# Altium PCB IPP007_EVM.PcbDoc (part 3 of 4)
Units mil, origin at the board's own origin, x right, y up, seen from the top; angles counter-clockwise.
Board outline 3500.95 x 3103 mil, 6 copper layers (Top Layer, Int1 (GND), Int2 (Sign), Int3 (Sign), Int4 (GND), Bottom Layer), stack 61.068 mil thick; 257 components, 132 nets, 1052 pads, 535 vias.
Unrouted connection lines stored in the file: 3.
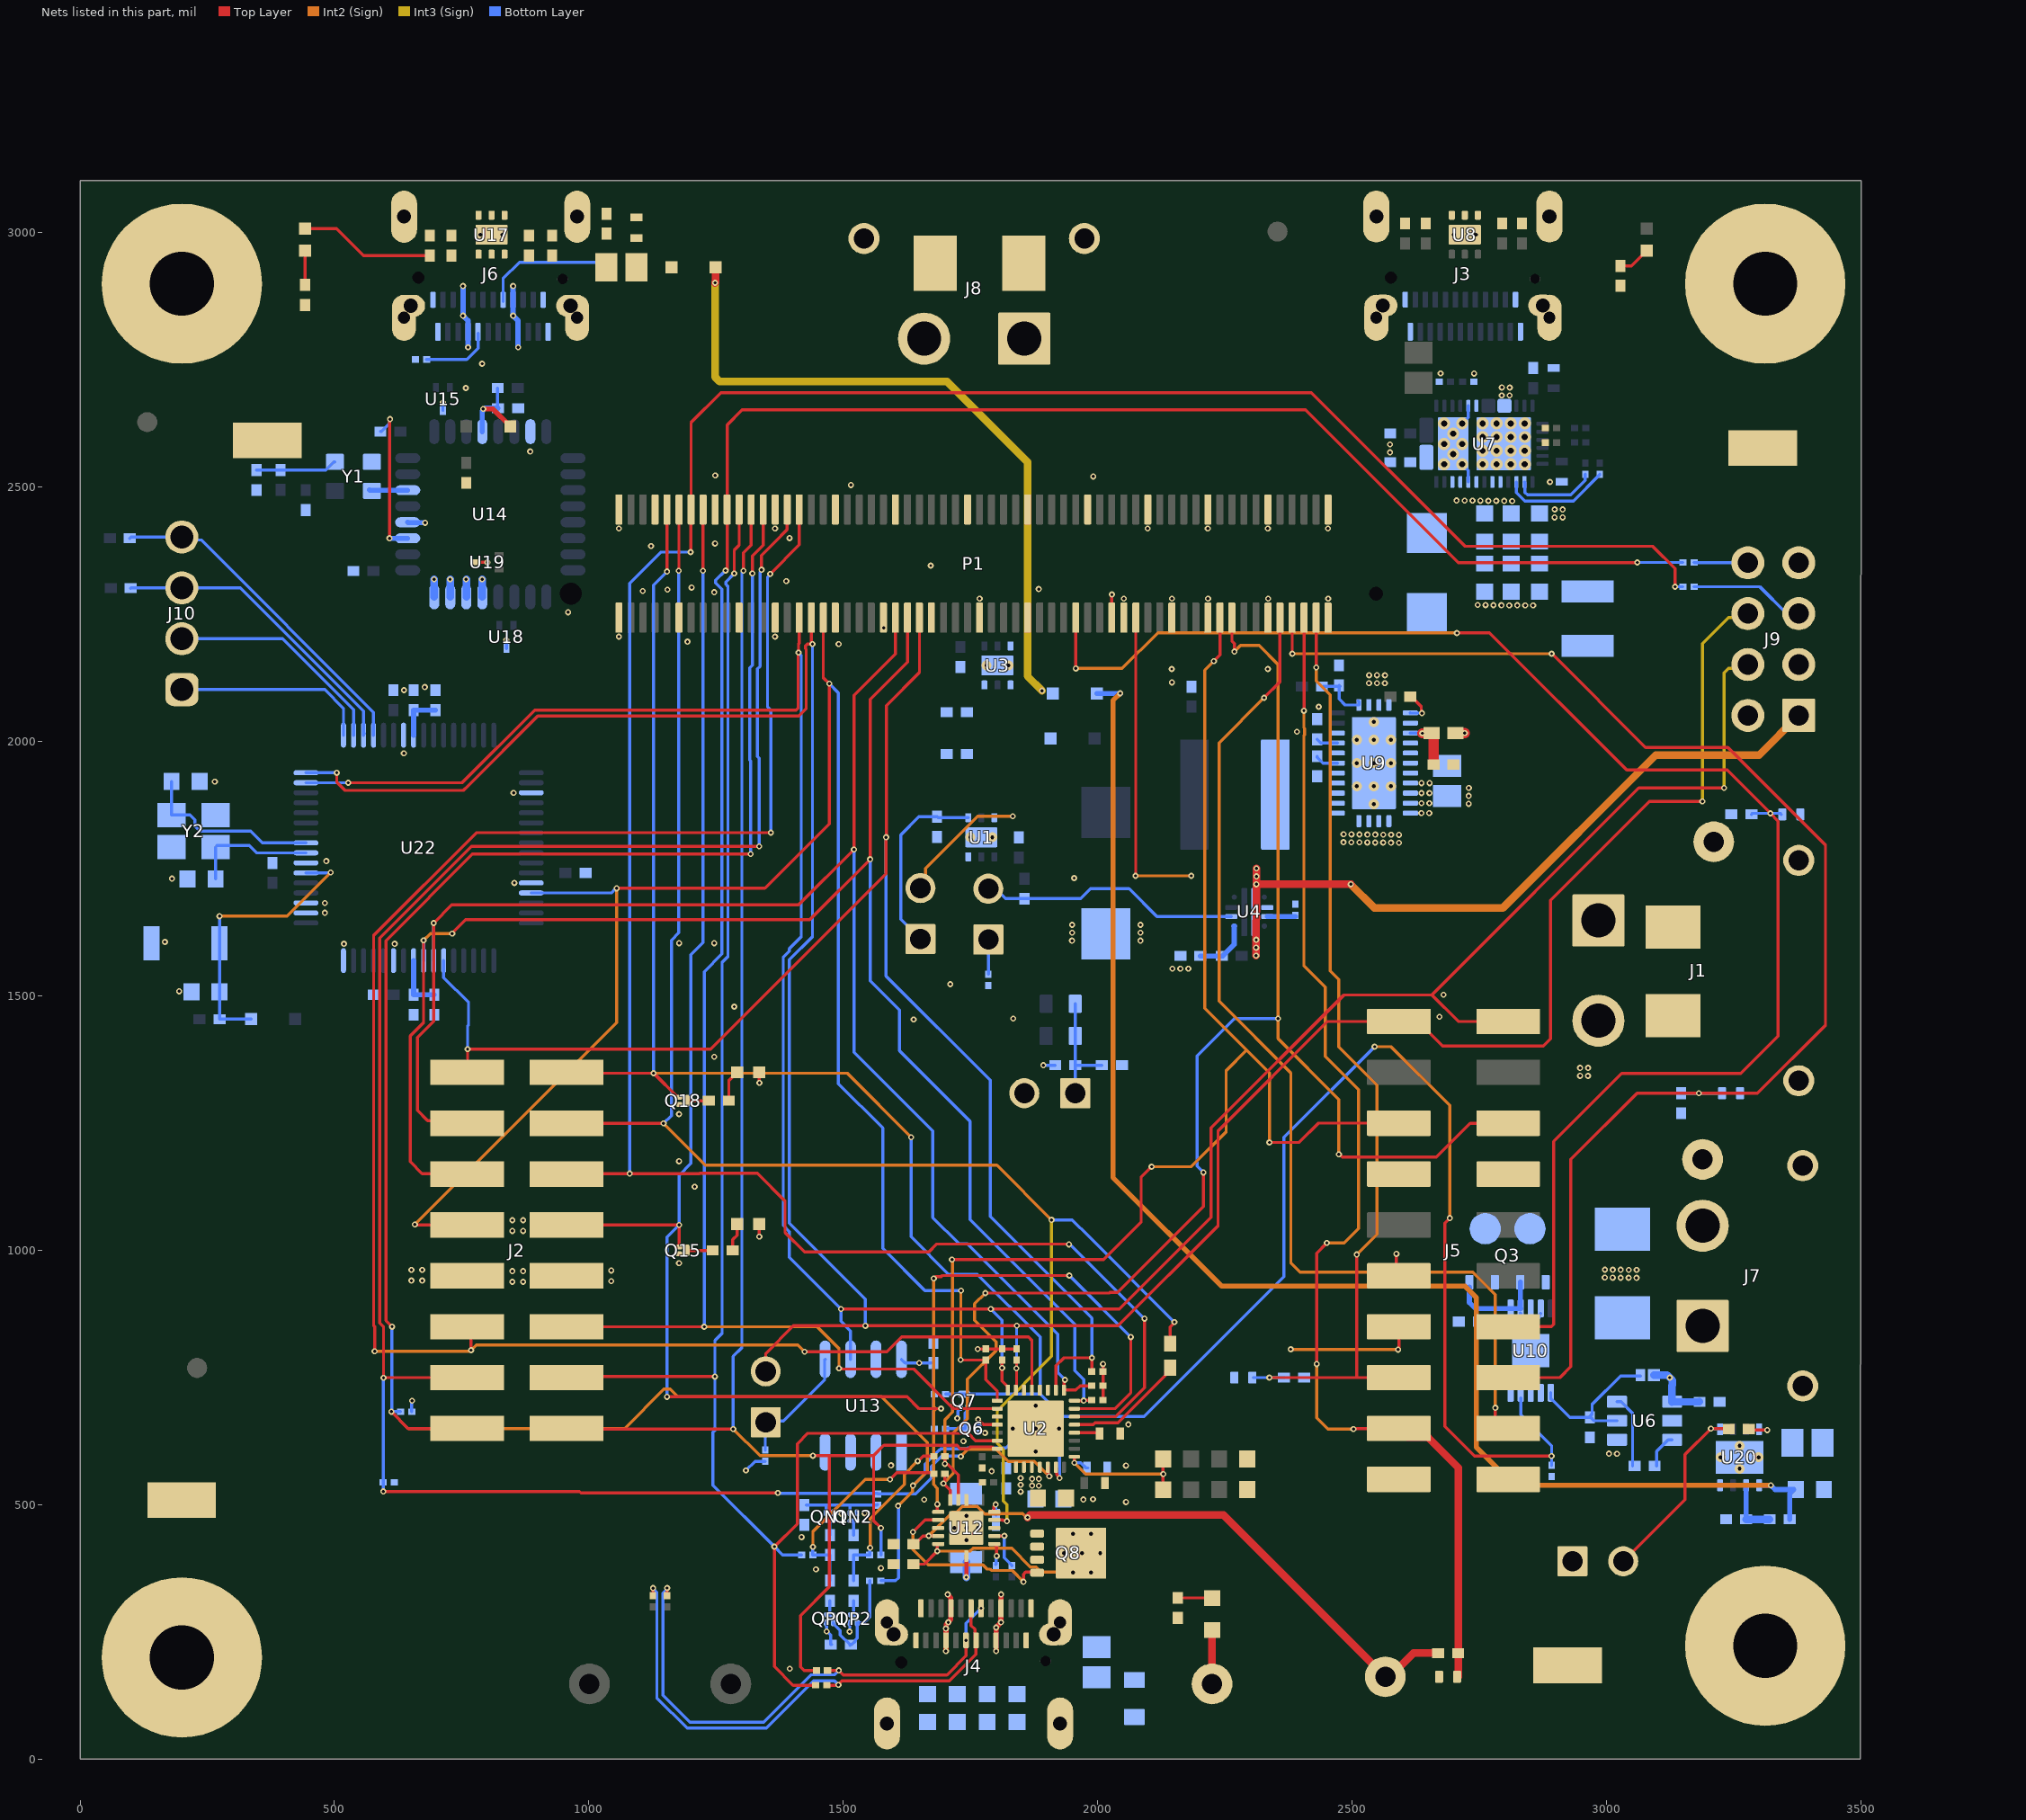
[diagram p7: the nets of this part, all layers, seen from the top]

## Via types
v1: diameter 12, hole 6, Top Layer to Bottom Layer, tented both sides, 471 vias
v2: diameter 19.68, hole 7.87, Top Layer to Bottom Layer, tented both sides, 34 vias
v3: diameter 23.62, hole 11.81, Top Layer to Bottom Layer, 24 vias
v4: diameter 19.68, hole 7.87, Top Layer to Bottom Layer, 6 vias

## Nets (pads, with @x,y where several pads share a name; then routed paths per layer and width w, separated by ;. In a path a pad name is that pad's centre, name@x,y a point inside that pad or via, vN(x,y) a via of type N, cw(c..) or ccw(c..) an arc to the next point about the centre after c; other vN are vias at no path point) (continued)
GND: C1.2 C2.2 C3.2 C4.2 C5.2 C6.2 C7.1 C12.2 C13.2 C14.2 C15.2 C16.2 C17.2 C18.1 C19.1 C20.2 C21.2 C22.2 C23.2 C24.2 C25.2 C26.2 C27.2 C28.2 C30.2 C31.2 C34.2 C35.2 C36.2 C37.1 C38.2 C39.2 C40.2 C41.2 C42.2 C43.2 C44.2 C45.1 C46.1 C47.2 C48.2 C49.2 C50.2 C51.2 C52.2 C53.2 C54.2 C55.2 C56.2 C57.2 C58.2 C59.2 C60.2 C61.2 C62.2 C63.2 C64.2 C65.2 C66.2 C82.2 C83.2 C84.2 C85.2 C86.2 C87.2 C88.2 C89.1 C90.2 C91.2 D3.2 D20.2 D22.2 H1.1 H2.1 H3.1 H4.1 J1.1 J1.3 J1.4 J2.7 J2.8 J3.A1 J3.A12 J3.B1 J3.B12 J3.S1 J3.S2 J3.S3 J3.S4 J4.A1 J4.A12 J4.B1 J4.B12 J4.S1 J4.S2 J4.S3 J4.S4 J5.A04 J5.A10 J5.B04 J5.B10 J6.A1 J6.A12 J6.B1 J6.B12 J6.S1 J6.S2 J6.S3 J6.S4 J7.1 J7.3 J7.4 J8.1 J8.3 J8.4 J9.2 J9.3 J13.1 J15.2 P1.1 P1.2 P1.8 P1.11 P1.18 P1.21 P1.27 P1.28 P1.37 P1.38 P1.45 P1.48 P1.53 P1.60 P1.61 P1.69 P1.70 P1.80 P1.85 P1.90 P1.93 P1.99 P1.100 P1.109 P1.110 P1.119 P1.120 Q6.2 Q7.2 Q15.2@1177.31,993.11 Q18.2@1177.31,1287.22 QN1.2@1480.57,484.04 QN2.2@1527.21,484.04 R3.1 R8.1 R9.1 R10.1 R13.1 R14.1 R15.1 R22.2 R23.1 R29.1 R32.1 R52.1 R54.2 R55.2 R56.1 R59.2 R63.1 R67.1 R69.1 R70.1 R73.1 R74.1 R80.1 R81.1 R95.1 S2.1 TP7.1 TP10.1 TP13.1 TP14.1 U1.3 U1.7@1771.37,1812.01 U2.11 U2.12 U2.14 U2.19 U2.33 U3.3 U3.7@1803.14,2149.77 U4.8 U6.2 U6.4 U7.11 U7.12 U7.14 U7.16 U7.17 U7.31 U7.34 U7.35 U7.39 U7.@2799.49,2660.04 U8.1 U8.2 U8.3 U8.7@2721.65,2996.38 U9.7 U9.9 U9.13 U9.14 U9.15 U9.17 U9.19 U9.23 U9.24 U9.25 U9.26 U9.27 U9.28 U9.29 U9.30 U9.31 U10.2 U10.3 U10.5 U10.11 U12.8 U12.13 U12.18 U12.21 U13.1 U13.2 U13.3 U13.4 U13.7 U14.7 U14.21 U14.22 U14.23 U14.24 U14.28 U15.3 U17.1 U17.2 U17.3 U17.7@808.77,2996.38 U18.3 U19.3 U20.4 U20.9@3261.67,593.38 U22.3 U22.12 U22.27 U22.32 U22.34 U22.35 U22.39 U22.55 Y1.2 Y2.2 Y2.4 | length 270.4
  Top Layer w6: U19.3@778.01,2352.37 v1(800.65,2352.37)
  Bottom Layer w6: U15.3@713.1,2651.02 U15.3@713.17,2650.95 ; U15.3@713.2,2650.98 v1(713.22,2666.33) ; v1(837.7,2199.65) 838.03,2199.32 U18.3@838.03,2183.19 ; QN1.2@1480.57,484.04 1481.43,483.18 1495.65,483.18 v1(1496.51,482.32) ; QN2.2@1527.21,484.04 QN2.2@1528.07,483.18 ; v1@1723.98,671.62 v1(1723.98,670) 1725.13,671.15 1725.13,683.89 1730.69,689.44 Q7.2@1730.69,691.92
  Bottom Layer w10: U14.28@643.96,2431.18 644.58,2430.55 677.7,2430.55 v1(678.08,2430.17)
  Bottom Layer w15: U14.24@696.12,2284.52 v1@696.12,2318.76 ; U14.23@727.62,2284.52 v1@727.62,2318.76 ; U14.22@759.11,2284.52 v1@759.11,2318.76 ; U14.21@790.61,2284.52 v1@790.61,2318.76
  other v1: 1394.96,177.91 1446.33,373.12 1574.01,375.45 1418.16,436.56 1542.17,483.18 2055.61,505.36 1659.11,510 1972.1,510.34 1991.02,510.86 1791.84,566 1594.02,577.52 2055.61,577 3005.1,600.47 3020.68,600.32 1736.18,625.11 1778.63,641.38 2060.44,657.88 849.63,938.22 870.71,938.22 1043.92,939.42 651.29,940.7 672.37,940.7 3012.4,946.42 3027.98,946.27 3043.57,946.13 3059.15,945.98 2996.81,946.57 849.63,959.3 870.71,959.3 1043.92,960.49 651.29,961.78 672.37,961.78 2996.96,962.15 3012.54,962 3028.13,961.86 3043.71,961.71 3059.3,961.56 1177.16,975 849.63,1038.22 870.71,1038.22 849.63,1059.3 870.71,1059.3 1207.91,1125.07 1177.16,1175.19 1177.16,1267.81 2948.09,1343.2 2963.68,1343.06 2948.24,1358.79 2963.83,1358.64 1246.41,1380.59 1638.42,1453.92 1833.96,1455.74 2671.96,1459.18 1285.75,1479 2679.84,1502.51 194.93,1509.28 1710.52,1523.24 2147.05,1553.9 2162.63,1553.75 2178.21,1553.6 518.63,1602.61 618.31,1602.61 1177.48,1603.91 1246.41,1603.91 166.86,1606.29 1949.6,1608.76 2083.99,1608.76 1949.75,1624.35 2084.14,1624.35 1949.89,1639.93 2084.28,1639.93 481.24,1663.59 481.24,1682.92 853.6,1722.31 180.71,1730.75 1953.9,1731.82 484.08,1765.14 2576.72,1801.4 2592.31,1801.25 2483.22,1802.28 2498.8,1802.14 2514.39,1801.99 2529.97,1801.84 2545.55,1801.69 2561.14,1801.55 2530.12,1817.43 2545.7,1817.28 2561.29,1817.13 2576.87,1816.98 2592.45,1816.84 2483.36,1817.87 2498.95,1817.72 2514.53,1817.57 2636.19,1859.44 2651.77,1859.44 2729.18,1877.84 2636.33,1879.12 2651.92,1879.12 2729.32,1893.42 852.02,1899.45 2636.48,1898.81 2652.06,1898.81 2729.47,1909.01 2636.63,1918.49 2652.21,1918.49 264.97,1921.52 636.35,1976.98 2391.69,2019.56 2434.47,2068.55 636.79,2101.18 677.5,2107.17 2533.31,2115.02 2548.9,2114.87 2564.48,2114.72 2146.07,2116.32 2549.04,2130.46 2564.63,2130.31 2533.46,2130.6 2145.6,2142.8 2334.57,2142.8 1491,2191.95 1193.8,2196.41 1058.96,2206.34 1366.05,2206.34 1579.23,2223.63 959.2,2254.31 2746.77,2268.5 2762.36,2268.35 2777.94,2268.2 2793.52,2268.05 2809.11,2267.91 2824.69,2268.05 2840.28,2267.91 2855.86,2267.76 1768.09,2281.06 2051.56,2281.06 2146.04,2281.06 2216.91,2281.06 2335.02,2281.06 2453.13,2281.06 1246.41,2293.71 1105.85,2296.05 1154.69,2298.74 1884.18,2299.8 1201.97,2302.81 1388.12,2315.56 695.74,2319.14 727.23,2319.14 758.73,2319.14 790.23,2319.14 1671.87,2345.95 1122.19,2384.45 1247.94,2389.41 1394.52,2400.08 1058.96,2418.94 1366.05,2418.94 2098.33,2418.94 2216.44,2418.94 2334.55,2418.94 2452.66,2418.94 2898.2,2440.79 2913.78,2440.65 2898.34,2456.38 2913.93,2456.23 2752.35,2473.45 2767.93,2473.3 2783.52,2473.16 2799.1,2473.01 2814.68,2472.86 2705.59,2473.89 2721.18,2473.74 2736.76,2473.6 1515.14,2504.28 2888.87,2510.43 1991.27,2521.19 1248.41,2523.19 2574.55,2568.56 884.72,2570.26 2574.7,2584.15 2794.19,2680.48 2809.77,2680.33 758.2,2694.98 2794.34,2696.06 2809.92,2695.91 2674.1,2723.81 2739.72,2723.57 790.24,2742.7
  other v2: 1741.78,430.8 1718.16,454.42 1741.78,454.42 1765.4,454.42 1741.78,478.04 3261.67,570.74 3224.27,593.38 3299.07,593.38 1878.59,604.31 3261.67,616.01 1833.31,649.59 1878.59,649.59 1923.86,649.59 1878.59,694.86 1749.72,1812.01 1793.02,1812.01 2542.86,1877.16 2509.4,1912.2 2542.86,1912.2 2576.32,1912.2 2509.4,1957.87 2542.86,1957.87 2576.32,1957.87 2509.4,2003.53 2542.86,2003.53 2576.32,2003.53 2542.86,2038.57 1781.48,2149.77 1824.79,2149.77 787.12,2996.38 830.43,2996.38 2700,2996.38 2743.31,2996.38
  other v3: 2756.77,2545.08 2784.33,2545.08 2811.89,2545.08 2839.45,2545.08 2756.77,2571.85 2784.33,2571.85 2811.89,2571.85 2839.45,2571.85 2756.77,2598.62 2784.33,2598.62 2811.89,2598.62 2839.45,2598.62 2756.77,2625.39 2784.33,2625.39 2811.89,2625.39 2839.45,2625.39
GPIO4: J2.3 P1.22 R25.1 R78.1 U2.22 | length 3420.8
  Top Layer w6: J2.3@957.8,751.92 v1(1247.81,751.92) ; v1(1285.75,2330.45) 1285.75,2376.09 1295.42,2385.75 P1.22@1295.42,2456.3 ; R78.1@1442.75,145.39 1401.45,145.39 1364.61,182.23 v1(1364.61,417.78) 1409.58,462.74 1409.58,619.6 1430.49,640.52 1745.3,640.52 1759.85,625.97 U2.22@1802.8,625.97
  Bottom Layer w6: v1(1285.75,2330.45) 1269.29,2313.98 1269.29,2309.01 1273.41,2304.89 1273.41,1577.6 1261.88,1566.07 1261.88,837.4 1247.81,823.32 v1(1247.81,751.92) 1247.81,646.23 1244.02,642.44 1244.02,538.37 v1(1364.61,417.78) 1381.02,401.37 R25.1@1418.16,401.37
GPIO5: J2.1 P1.24 R26.2 R77.1 U2.23 | length 3377.5
  Top Layer w6: J2.1@956.9,648.98 v1(1283.72,648.98) ; v1(1303.86,2335.91) 1303.86,2371.1 1319.04,2386.28 P1.24@1319.04,2456.3 ; v1(1440.37,596.42) 1472.92,596.42 ; R77.1@1447.05,174.21 1423.27,174.21 1416.06,181.42 1416.06,282.26 1472.92,339.11 1472.92,596.42 ; v1(1574.01,454.42) 1559.65,468.78 1559.65,596.42 ; U2.23@1802.8,610.22 1795.91,610.22 1792.16,613.97 1749.91,613.97 1746.05,610.11 1729.97,610.11 1723.37,616.71 1579.94,616.71 1559.65,596.42 ; 1472.92,596.42 1559.65,596.42
  Int2 (Sign) w6: v1(1283.72,648.98) 1336.29,596.42 v1(1440.37,596.42)
  Bottom Layer w6: v1(1283.72,648.98) 1283.72,791.61 1300.75,808.63 1300.75,1526.59 ; 1300.72,1526.62 1300.72,1946.78 ; 1300.75,1946.81 1300.75,2329.4 1300.75,2331.18 1303.86,2334.29 v1(1303.86,2335.91) ; R26.2@1574.01,401.37 v1(1574.01,454.42)
GPIO6: J2.2 P1.26 R19.1 R24.1 U2.31 | length 4479.8
  Top Layer w6: v1(612,683) 645,650 J2.2@761,650 ; v1(613.17,850.04) 601,862.2 601,1608.92 771.08,1779 v1(1318.1,1779) ; v1(1321.33,2330.45) 1321.33,2364.94 1342.66,2386.27 P1.26@1342.66,2456.3 ; U2.31@1917.96,573.8 1918.9,572.86 1918.9,563.34 1920,562.23 1920,559.11 1925.12,553.99 v1(1925.12,552.6)
  Int2 (Sign) w6: v1(612,683) 645,650 1070.32,650 1147.47,727.15 1159.9,727.15 1174.9,712.15 1575.43,712.15 1665.33,622.25 1665.33,565.83 v1(1637.18,537.68) 1636.03,536.54 1636.03,526.16 v1(1607.88,498)
  Bottom Layer w6: v1@612.58,850.04 612.58,683.58 v1(612,683) R19.1@629.77,683 ; v1(1318.1,1779) 1318.1,1961.86 1316.28,1963.68 1316.28,2144.91 1321.33,2149.96 v1(1321.33,2330.45) ; R24.1@1574.01,350.81 1602.67,350.81 1608.41,356.54 1608.41,497.47 v1(1607.88,498) ; v1(1637.18,537.68) 1661.21,561.71 1661.21,580.15 1688.56,607.5 1688.84,607.5 1691.44,610.11 1742.39,610.11 1744.32,612.04 1819.59,612.04 1838.3,630.74 1896.29,630.74 1925.04,601.99 1925.12,601.99 v1(1925.12,552.6)
GPIO7: J2.4 P1.30 R29.2 R30.1 U2.30 | length 4164.2
  Top Layer w6: v1(596,526.3) 981.6,526.3 984.66,523.24 v1(1371.41,523.24) ; J2.4@761,750 597,750 v1(596.5,749.5) 596.5,849.73 589,857.23 589,1613.89 769.11,1794 v1(1334.65,1794) ; v1(1339.53,2337.91) 1339.53,2366.16 1364.02,2390.65 1364.02,2390.78 1389.9,2416.67 P1.30@1389.9,2456.3 ; U2.30@1902.21,573.8 1903.03,572.98 v1@1903.03,556.02
  Int2 (Sign) w6: v1(1731.04,595.11) 1745.15,609.22 1800.74,609.22 1824.5,585.47 1875.55,585.47 v1(1905,556.02)
  Bottom Layer w6: v1(596,526.3) v1@596,749.5 ; v1(1334.65,1794) 1334.65,1967.6 1331.28,1970.97 1331.28,2142.94 1336.33,2147.99 1336.33,2331.39 1336.33,2333.09 1339.53,2336.29 v1(1339.53,2337.91) ; v1(1371.41,523.24) 1372.35,522.3 1567.05,522.3 R30.1@1567.99,521.36 1642.07,521.36 1673.21,552.49 1673.21,575.18 1693.53,595.5 v1@1730.55,595.5
GPIO.F\L\T\: J2.13 P1.12 R31.2 U12.9 | length 3291.9
  Top Layer w6: J2.13@955.88,1250 956.23,1249.65 v1(1146.89,1249.65) ; v1(1176.7,2335.91) 1177,2336.21 1177,2456 P1.12@1177.31,2456.3 ; U12.9@1796.9,470.17 1812.79,470.17 1813.87,469.09 1820.74,469.09 v1(1821.88,467.95) ; R31.2@2142.5,816.78 2142.5,849.28 2150.82,857.59 v1(2150.82,859.22)
  Int2 (Sign) w6: v1(1146.89,1249.65) 1229.03,1167.51 1801.87,1167.51 v1(1909.42,1059.96)
  Int3 (Sign) w6: v1(1821.88,467.95) 1821.88,500.27 1814.56,507.59 1814.56,608.7 1802.8,620.46 1802.8,685.02 1909.42,791.64 v1(1909.42,1059.96)
  Bottom Layer w6: v1(1146.89,1249.65) 1162.16,1264.93 1162.16,1609.81 1176.7,1624.35 v1(1176.7,2335.91) ; v1(1909.42,1059.96) 1950.05,1059.96 1983.2,1026.81 v1(2150.82,859.22)
GPIO.GPIO1: J2.11 P1.14 R137.1 U2.6 | length 5314.5
  Top Layer w6: J2.11@955.88,1150 956.88,1151 v1(1080.13,1151) 1217.53,1151 1217.94,1151.41 1331.28,1151.41 1385.64,1097.06 1385.64,1035.4 1424.2,996.84 1668.38,996.84 1684.08,1012.54 1943,1012.54 v1(1943.73,1011.81) ; v1(1199.96,2372.41) 1200.45,2372.89 1200.45,2455.82 P1.14@1200.93,2456.3 1200.93,2627.04 1259.88,2686 2419.88,2686 2721.88,2384 3090.89,2384 3134.87,2340.01 v1(3134.87,2304.5) ; U2.6@1954.38,673.21 2035.36,673.21 2092.25,730.1 v1(2092.25,866)
  Bottom Layer w6: v1(1080.13,1151) 1080.13,2310.96 1141.57,2372.41 v1(1199.96,2372.41) ; v1(1943.73,1011.81) 1945.09,1011.81 2090.9,866 v1(2092.25,866) ; v1(3134.87,2304.5) 3134.92,2304.45 R137.1@3150.19,2304.45
GPIO.GPIO2: J2.9 P1.16 Q15.1@1177.31,1006.89 U2.7 U12.16 | length 3736.1
  Top Layer w6: J2.9@955.88,1050 v1(1177.31,1050) Q15.1@1177.31,1006.89 ; v1(1153.68,712.15) 1625.78,712.15 1648.97,688.96 v1(1692.33,688.96) ; v1(1224.32,2335.91) 1224.43,2336.03 P1.16@1224.43,2456.18 ; v1(1678,944.77) 1681.94,948.71 1692.95,948.71 1694.83,950.6 v1(1944.22,950.6) ; v1(1685,500.97) 1685,486.85 1685.94,485.92 U12.16@1686.66,485.92 ; U2.7@1954.38,688.96 2034.14,688.96 2065.1,719.92 v1(2065.1,829.72)
  Int2 (Sign) w6: v1(1678,944.77) 1678,693.34 1682.38,688.96 ; v1(1685,500.97) 1685,532.54 1677.33,540.22 1677.33,683.91 1682.38,688.96 ; v1(1692.33,688.96) 1682.38,688.96
  Bottom Layer w6: v1(1153.68,712.15) 1153.68,1026.38 v1(1177.31,1050) 1177.31,1147.52 1200.81,1171.02 1200.81,1581.49 1224.32,1605 v1(1224.32,2335.91) ; v1(1944.22,950.6) v1(2065.1,829.72)
GPIO.GPIO3: J2.5 P1.20 R139.1 U2.18 | length 4758.2
  Top Layer w6: J2.5@955.88,850 956.01,849.87 v1(1226.7,849.87) ; v1(1268.72,2336.28) 1269.3,2335.71 1270.4,2335.71 1271.79,2337.1 P1.20@1271.79,2456.3 1271.79,2622.61 1301.37,2652.19 2408.32,2652.19 2708.6,2351.91 3060.15,2351.91 v1(3060.49,2352.25) ; v1(1491.68,768.25) 1496.3,768.25 1494.9,766.85 1638.68,766.85 1716.57,688.96 U2.18@1802.8,688.96 ; v1(1226.7,849.87) 1226.91,849.66 v1(1226.7,849.87)
  Int2 (Sign) w6: v1(1226.7,849.87) 1449.03,849.87 1491.68,807.22 v1(1491.68,768.25)
  Bottom Layer w6: v1(1226.7,849.87) 1226.7,1547.86 1261.41,1582.57 1261.41,2299.92 1249.37,2311.96 1249.37,2316.93 v1(1268.72,2336.28) ; v1(3060.49,2352.25) R139.1@3150.19,2352.25
GPIO.GPIO11: J2.6 P1.32 U2.13 | length 3810.2
  Top Layer w6: v1(579,801.54) 579,850.26 577,852.26 577,1618.86 779.14,1821 v1(1357.64,1821) ; J2.6@761,850 768.58,842.42 v1(768.58,803.92) ; v1(1356.53,2329.73) 1413.53,2386.73 P1.32@1413.53,2456.3 ; v1(1424.01,800.95) 1586.09,800.95 1614.86,829.72 1863.8,829.72 1870.71,822.81 U2.13@1870.71,725.37
  Int2 (Sign) w6: v1(579,801.54) 764.57,801.54 766.96,803.92 v1(768.58,803.92) 778.76,814.1 1053.96,814.1 1410.86,814.1 v1(1424.01,800.95)
  Bottom Layer w6: v1(1356.53,2329.73) 1356.53,2328.11 1351.05,2322.62 1351.05,2068.73 1357.64,2062.13 v1(1357.64,1821)
GPIO_NF: QN1.1@1466.79,484.04 QN2.1@1513.43,484.04 R30.2 R52.2 | length 173.1
  Bottom Layer w6: R52.2@1427.27,499.54 1427.43,499.7 1469.89,499.7 ; QN1.1@1466.79,484.04 1466.79,496.59 1469.89,499.7 ; QN2.1@1513.43,484.04 1513.43,498.62 1512.36,499.7 ; R30.2@1566.96,500.34 1566.32,499.7 1512.36,499.7 ; 1469.89,499.7 1512.36,499.7
GPIO_PF: QP1.1@1480.57,268 QP2.1@1527.21,267.99 R24.2 R47.1 | length 208.3
  Bottom Layer w6: QP1.1@1480.57,268 1480.57,266.03 1494,252.6 1494,244.23 R47.1@1512.93,225.3 ; R47.1@1513.43,223.83 R47.1@1514.9,225.3 1516.87,225.3 1523.71,232.14 1523.71,234.11 1527.36,237.75 QP2.1@1527.36,267.99 ; QP2.1@1527.21,267.99 QP2.1@1527.36,267.99 ; R24.2@1551.96,350.81 1551.96,279.05 1540.9,267.99 QP2.1@1527.36,267.99
HV_VSYS: C30.1 C31.1 D1.1 D3.1 D20.1 J1.2 J8.2 R20.2 R66.2 TP4.1 U9.20 U9.21 U9.22 | length 22.1
  Top Layer w20: R20.2@2699.52,2016.87 2699.57,2016.92 v1(2721.65,2016.92)
HV_VSYS_D10: J5.B07 P1.77 R66.1 R70.2 | length 3125.7
  Top Layer w6: P1.77@1956.83,2243.7 1957.03,2243.51 1957.03,2143.94 v1(1957.22,2143.74) v1@1957.03,2143.55 ; v1(2705.98,2213.42) 2705.23,2214.17 2770,2214.17 3039.88,1944.29 3237.78,1944.29 v1@3322.24,1859.83 ; J5.B07@2806.96,850 2891.62,850 2896.52,854.9 2896.52,1214.02 3030.12,1347.61 3263.95,1347.61 3337.4,1421.06 3337.4,1843.95 v1(3322.24,1859.11)
  Int2 (Sign) w6: v1(1957.22,2143.74) 2048.12,2143.74 2118.55,2214.17 2705.23,2214.17 v1(2705.98,2213.42)
  Bottom Layer w6: R66.1@3284.82,1857.16 3286.78,1859.11 3341.79,1859.11 R70.2@3343.74,1857.16
I2Cc_SCL: J5.B01 J9.4 P1.31 R42.2 U2.16 U13.6 U22.47 | length 5571
  Top Layer w6: v1(527.16,1919.14) 751.03,1919.14 894.01,2062.12 1407.62,2062.12 1411.14,2065.63 1411.14,2174.13 v1(1412.08,2175.07) 1412.08,2191.62 1413.53,2193.07 P1.31@1413.53,2243.7 ; v1(1495.54,884.75) v1(1790.16,884.75) 2042.83,884.75 2222.98,1064.9 2222.98,1241 2484,1502.02 2656.7,1502.02 ; R42.2@1812.18,784.2 v1(1812.18,769.16) 1812.18,743.56 1822.73,733 1822.73,726.11 U2.16@1823.47,725.37 ; J5.B01@2806.96,1450 2708.72,1450 2656.7,1502.02 ; v1(3231.36,1909.01) 3063.69,1909.01 2656.7,1502.02
  Int2 (Sign) w6: v1(3231.36,1909.01) v1@3231.85,1908.52
  Int3 (Sign) w6: v1(3231.36,1909.01) 3231.36,2135.11 3239.99,2143.73 3270.11,2143.73 J9.4@3277.95,2151.57
  Bottom Layer w6: U22.47@443.94,1919.14 v1(527.16,1919.14) ; v1(1412.08,2175.07) 1412.08,2173.86 1417.39,2168.55 1417.39,1616.33 1394.12,1593.06 1394.12,1588.38 1382.12,1576.38 1382.12,1048.91 1394.12,1036.91 1394.12,986.17 v1(1495.54,884.75) 1495.54,860.68 1514.41,841.8 U13.6@1514.41,786.05 ; v1(1790.16,884.75) 1812.18,862.74 v1(1812.18,769.16)
I2Cc_SDA: J5.A01 J9.6 J14.2 P1.33 R43.2 U2.15 U22.48 | length 5849.4
  Top Layer w6: v1(504.58,1938.82) 504.58,1920.5 520.94,1904.14 753,1904.14 761.79,1912.92 762.35,1912.92 899.55,2050.12 1412.59,2050.12 1427.08,2064.6 1427.08,2181.28 1425.69,2182.67 1425.69,2188.27 1429.38,2191.95 v1(1439.53,2191.95) ; J14.2@1347.65,762.15 1347.65,797.61 1401.92,851.88 v1(1543.61,851.88) 1543.67,851.94 1839.6,851.94 1839.66,851.99 v1(1841.28,851.99) 2040.17,851.99 2236.62,1048.44 2236.62,1234.96 2451.66,1450 J5.A01@2554.4,1450 ; v1@1437.15,2195.96 P1.33@1437.15,2243.7 ; U2.15@1839.22,725.37 1840.16,726.31 1840.16,735.68 1840.71,736.23 R43.2@1840.71,784.2 ; J5.A01@2592,1450 2629.6,1450 2678.09,1401.5 2875.96,1401.5 2890.03,1415.58 2890.03,1688.24 3084.19,1882.41 v1(3188.52,1882.41)
  Int2 (Sign) w6: v1(1439.53,2191.95) v1@1440.68,2193.1
  Int3 (Sign) w6: v1(3188.52,1882.41) 3188.52,2192.44 3239.99,2243.91 3270.29,2243.91 J9.6@3277.95,2251.57
  Bottom Layer w6: U22.48@443.94,1938.82 v1(504.58,1938.82) ; v1(1439.53,2191.95) 1439.53,1616.82 1394.12,1571.4 1394.12,1053.88 1543.61,904.39 v1(1543.61,851.88) ; v1(1840.28,768.13) 1840.78,768.63 1840.78,851.49 v1(1841.28,851.99)
I2Ct_SCL: J2.14 P1.47 R36.2 U2.9 U22.23 | length 3241.7
  Top Layer w6: J2.14@761,1250 755.9,1255.1 683.07,1255.1 663.11,1275.06 663.11,1418.81 694.93,1450.62 v1(694.93,1643.37) 730.52,1678.96 1412.14,1678.96 v1(1520.98,1787.8) 1520.98,2090.71 1602.5,2172.24 P1.47@1602.5,2243.7 ; v1(1935.53,745.68) 1933.71,743.86 U2.9@1933.71,725.37 1956.89,725.37 1965.4,733.88 R36.2@1988.44,733.88
  Bottom Layer w6: U22.23@694.93,1569.73 v1(694.93,1643.37) ; v1(1520.98,1787.8) 1520.98,1389.62 1676.1,1234.51 1676.1,1064.56 1727.97,1012.7 1744.28,1012.7 1921.43,835.54 1921.43,759.78 v1(1935.53,745.68)
I2Ct_SDA: J2.12 P1.49 R37.2 U2.8 U22.24 | length 3329.7
  Top Layer w6: v1(675.11,1609.41) 675.11,1447.78 648.94,1421.6 648.94,1174.43 672.37,1151 760,1151 J2.12@761,1150 ; v1(731.42,1622.82) 731.42,1623.62 757.97,1650.17 1434.2,1650.17 v1(1552.79,1768.76) 1552.79,2082.75 1626.12,2156.09 P1.49@1626.12,2243.7 ; U2.8@1954.38,704.71 1971.52,704.71 1972.1,705.28 1987.86,705.28 R37.2@1988.44,705.85
  Int2 (Sign) w6: v1(675.11,1609.41) 688.52,1622.82 v1(731.42,1622.82)
  Bottom Layer w6: v1(675.11,1609.41) 675.24,1609.28 U22.24@675.24,1569.73 ; v1(1552.79,1768.76) 1552.79,1530.21 1610.54,1472.46 1610.54,1392.48 1749.25,1253.77 1749.25,1060.77 1954.98,855.03 1954.98,763.95 1972.52,746.42 v1(1972.52,704.71)
I\2\C\c\_\I\R\Q\: J2.10 P1.35 R44.2 U2.17 U22.13 | length 3597.5
  Top Layer w6: v1(658.11,1051.07) 659.19,1050 J2.10@761,1050 ; v1(1054.5,1711.62) 1345.91,1711.62 1472.59,1838.3 v1(1472.59,2113.94) 1460.68,2125.85 1460.68,2243.61 P1.35@1460.77,2243.7 ; v1(1730.69,784.93) 1731.05,784.57 1779.81,784.57 R44.2@1780.17,784.2 1780.17,745.68 1802.8,723.05 U2.17@1802.8,704.71
  Int2 (Sign) w6: v1(658.11,1051.07) 1054.5,1447.46 v1(1054.5,1711.62) ; v1(1730.69,784.93) 1731.18,785.42 1731.18,920.34 v1(1731.67,920.83)
  Bottom Layer w6: U22.13@886.85,1702.6 1043.86,1702.6 1052.88,1711.62 v1(1054.5,1711.62) ; v1(1472.59,2113.94) 1490.6,2095.93 1490.6,1327.43 1577.5,1240.53 1577.5,1003.8 1660.46,920.83 v1(1731.67,920.83)
I\2\C\t\_\I\R\Q\: J2.16 P1.51 R38.2 U2.10 U22.22 | length 3079.4
  Top Layer w6: J2.16@761,1350 761.79,1350.79 v1(761.79,1395.7) 1239.45,1395.7 1584.29,1740.55 v1(1584.29,1812.01) 1584.99,1812.71 1584.99,2070.92 1649.75,2135.68 P1.51@1649.75,2243.7 ; U2.10@1917.96,725.37 1917.96,773.09 1933.81,788.94 v1(1988.76,788.94) 1988.6,788.77 1988.6,762.14 R38.2@1988.44,761.98
  Bottom Layer w6: U22.22@714.61,1569.73 714.61,1536.06 763.54,1487.13 763.54,1443.11 761.79,1441.35 v1(761.79,1395.7) ; v1(1584.29,1812.01) 1584.29,1539.14 1789.04,1334.39 1789.04,1066.45 1988.76,866.73 v1(1988.76,788.94)
ICD_TCK: J10.4 R96.1 U22.52 | length 667.7
  Bottom Layer w6: R96.1@97.81,2399.68 100.35,2402.22 J10.4@200,2402.22 205.82,2396.4 237.97,2396.4 576.82,2057.55 U22.52@576.82,2012.64
ICD_TDI: J10.2 U22.50 | length 445.5
  Bottom Layer w6: J10.2@200,2202.22 398.21,2202.22 537.45,2062.98 U22.50@537.45,2012.64
ICD_TDO: J10.1 U22.49 | length 385.9
  Bottom Layer w6: J10.1@200,2102.22 481.24,2102.22 517.76,2065.69 U22.49@517.76,2012.64
ICD_TMS: J10.3 R97.1 U22.51 | length 608
  Bottom Layer w6: R97.1@99.69,2301.62 100.28,2302.22 J10.3@200,2302.22 315.18,2302.22 557.13,2060.26 557.13,2030.48 557.13,2016.15 U22.51@557.13,2012.64 ; U22.51@557.13,2014.38 U22.51@558.91,2016.15
LDO_1V5: C46.2 U2.4 | length 50.8
  Top Layer w6: U2.4@1954.38,641.71 2002.61,641.71 C46.2@2004.43,639.9
LDO_3V3: C4.1 C45.2 C49.1 C53.1 D12.2 D23.1 D26.1 J5.A06 J9.7 P1.83 QP1.2@1466.79,268 QP2.2@1513.43,267.99 R2.2 R6.2 R7.2 R19.2 R34.2 R35.2 R36.1 R37.1 R38.1 R42.1 R43.1 R44.1 R47.2 R91.2 U2.1 U6.1 U12.10 U13.8 | length 1091.4
  Top Layer w6: D23.1@1334.59,1051.58 1335.1,1051.07 v1(1335.1,1027.2) ; v1@1334.59,1329.81 D26.1@1334.59,1350 ; v1(1764.32,806.25) R44.1@1780.17,806.25 R42.1@1812.18,806.25 R43.1@1840.71,806.25 ; v1@1796.23,497.01 1796.23,486.58 U12.10@1796.9,485.92 ; v1(1954.38,582.49) U2.1@1954.38,594.47 ; R37.1@2010.48,705.85 R36.1@2010.48,733.88 R38.1@2010.48,761.98 2010.48,776.56 v1(2010.57,776.65) ; P1.83@2027.7,2243.7 2027.7,2288.88 v1(2028.07,2289.25) ; R6.2@2128.53,529.5 R7.2@2128.53,589.75 ; v1(2587.32,993.18) 2587.32,954.68 J5.A06@2592,950
  Int2 (Sign) w6: v1(1954.38,582.49) 1976.23,560.64 v1(2128.98,560.64)
  Bottom Layer w6: R19.2@651.82,683 651.82,703.84 v1(652.39,704.41) ; v1(1308.67,567.35) 1326.71,585.39 R91.2@1346.76,585.39 ; QP1.2@1466.79,268 1467.28,267.5 v1(1467.28,251.31) 1467.77,250.82 1468.65,250.82 1475.53,243.93 R47.2@1475.53,225.3 R47.2@1477.5,225.3 ; v1(1512.36,250.82) 1512.9,251.36 1512.9,267.45 QP2.2@1513.43,267.99 ; U13.8@1614.41,786.05 1614.41,785.8 1621.55,778.66 v1(1649.44,778.66) C53.1@1677.33,778.66 R34.2@1677.33,649.59 ; v1(1799.8,500.57) 1800.08,500.29 1800.08,480.31 C49.1@1800.36,480.03 ; v1(1893.3,1363.98) 1893.37,1364.06 R2.2@1916.61,1364.06 ; v1(1954.38,582.49) 1967.02,582.49 1977.14,572.38 C45.2@1978.79,572.38 C45.2@1981.07,572.38
  Bottom Layer w15: D12.2@3093.61,755.19 3119.23,755.19 3129.76,744.67 3129.76,735.42 3129.1,734.76 3129.1,701.86 C4.1@3182.95,702.52
  other v1: 3124.5,749.93 1335.23,1329.17
NetC2_1: C2.1 C5.1 D2.1 D5.1 D10.1 J11.2 U1.6 U3.4 U3.6 | length 1617.6
  Top Layer w15: v1(1248.06,2901.77) 1249.13,2902.84 D10.1@1249.13,2932.28
  Int2 (Sign) w6: J11.2@1651.69,1712.05 1661.64,1722.01 1661.64,1750.58 1764.3,1853.24 v1(1833.32,1853.24)
  Int3 (Sign) w15: v1(1248.06,2901.77) 1248.06,2716.59 1256.85,2707.8 1703.98,2707.8 1862,2549.79 1862,2128.89 v1(1890.74,2100.14)
NetC7_2: C7.2 D12.1 U6.5 U10.1 | length 304.7
  Bottom Layer w6: U10.1@2890.57,720.1 2890.57,708.6 2893.57,705.6 2894.19,705.6 2927.86,671.93 C7.2@2967.29,671.93 2967.29,673.93 2971.83,678.47 2971.83,697.1 3027.93,753.19 D12.1@3067.04,753.19 ; C7.2@2968.29,672.93 2976.1,665.11 U6.5@3020.83,665.11
NetC8_2: C8.2 U10.9 | length 133
  Bottom Layer w6: C8.2@2749.46,855 2755.14,860.69 2860.66,860.69 2867.88,867.91 2867.88,872.88 U10.9@2870.89,875.89
NetC9_1: C9.1 U6.3 | length 68.7
  Bottom Layer w6: C9.1@3098.58,576.25 3098.58,605.08 3121.22,627.71 U6.3@3129.1,627.71
NetC9_2: C9.2 U6.6 | length 143.5
  Bottom Layer w6: U6.6@3020.83,702.52 3028.7,702.52 3051.34,679.88 C9.2@3051.34,576.25
NetC33_1: C33.1 L3.1 U9.1 U9.2 U9.3 U9.4 U9.5
NetC33_2: C33.2 U9.6 | length 46.2
  Bottom Layer w6: C33.2@2431.5,1971.24 2431.5,1969.27 2442.9,1957.87 U9.6@2471.01,1957.87
NetC36_1: C36.1 U9.8 | length 42.9
  Bottom Layer w6: C36.1@2431.5,2004.64 2431.5,2004.08 2438.35,1997.24 U9.8@2471.01,1997.24
NetC50_1: C50.1 U12.3 | length 71.8
  Top Layer w8: v1(1741.78,357.61) U12.3@1741.78,399.3
  Bottom Layer w6: C50.1@1741.33,387.49 C50.1@1741.78,387.04
  Bottom Layer w15: v1(1741.78,357.61) C50.1@1741.78,387.04
NetC57_1: C57.1 D13.2 R93.1 U14.4 | length 180.6
  Top Layer w10: v1(792.42,2654.03) 811.44,2654.03 D13.2@845.73,2619.74
  Bottom Layer w6: R93.1@820.82,2694.75 820.82,2655.93 C57.1@821.48,2655.28
  Bottom Layer w10: U14.4@790.61,2609.33 790.61,2649.42 796.47,2655.28 C57.1@821.48,2655.28
NetC60_1: C60.1 D5.2 R94.2 U20.1 | length 2853.1
  Int2 (Sign) w10: v1(2044.45,2095.05) 2030.04,2080.64 2030.04,1143.52 2243.72,929.84 2721.93,929.84 2744.36,907.41 2744.36,613.05 2819.16,538.26 v1(3322.98,538.26)
  Bottom Layer w10: D5.2@1998.64,2094.42 1998.95,2094.74 2044.13,2094.74 v1(2044.45,2095.05) ; U20.1@3300.05,538.26 v1(3322.98,538.26) 3331.4,529.84 3368.19,529.84 3360.23,521.89 R94.2@3360.23,471.34
NetC85_1: C85.1 C86.1 U22.25 | length 107.7
  Bottom Layer w10: U22.25@655.56,1569.73 C86.1@655.56,1502.47 C85.1@696.02,1502.47
NetC87_1: C87.1 C88.1 U22.56 | length 92.2
  Bottom Layer w10: U22.56@655.56,2012.64 C87.1@655.56,2061.81 C88.1@698.54,2061.81
NetD4_2: D4.2 R56.2 | length 67.8
  Top Layer w6: R56.2@442.28,2897.72 D4.2@442.28,2964.97 D4.2@442.67,2965.36
NetD6_2: D6.2 R15.2 | length 61.4
  Top Layer w6: R15.2@3027.59,2935.23 3049.36,2935.23 3073.2,2959.06 D6.2@3079.1,2959.06
NetD7_1: D7.1 R32.2 | length 67.4
  Top Layer w6: R32.2@2157.62,316.94 2221.38,316.94 2221.66,316.66 D7.1@2224.88,316.66
NetD23_2: D23.2 R149.2 | length 58
  Top Layer w6: R149.2@1280.65,1001.97 R149.2@1282.62,1000 1282.62,1021.35 1291.28,1030.01 D23.2@1291.28,1051.58
NetD26_2: D26.2 R152.2 | length 62.6
  Top Layer w6: R152.2@1275.12,1294.11 1275.12,1333.84 D26.2@1291.28,1350
NetJ6_A5: J6.A5 R55.1 | length 139.6
  Bottom Layer w6: R55.1@680.89,2751.22 760.01,2751.22 782.26,2773.47 J6.A5@782.26,2802.51
NetJ6_B5: J6.B5 R54.1 | length 245.3
  Bottom Layer w6: J6.B5@831.48,2865.5 831.48,2910.18 863.48,2942.19 R54.1@1018.82,2942.19
NetJ9_5: J9.5 R137.2 | length 204
  Bottom Layer w6: R137.2@3172.24,2304.45 3301.46,2304.45 J9.5@3354.33,2251.57
NetJ9_8: J9.8 R139.2 | length 82.4
  Bottom Layer w6: R139.2@3172.24,2352.25 3172.57,2351.91 3253.99,2351.91 J9.8@3254.33,2351.57
NetJ11_1: J11.1 R3.2 U1.4 | length 366.1
  Bottom Layer w6: J11.1@1651.69,1612.05 1613.16,1650.58 1613.16,1816.63 1648.67,1852.14 R3.2@1684.43,1852.14 ; R3.2@1686.18,1850.4 U1.4@1745.78,1850.4
NetJ12_1: J12.1 R59.1 | length 68
  Bottom Layer w6: R59.1@1785.2,1542.92 J12.1@1785.2,1610.94
NetJ12_2: J12.2 R58.1 U4.2 | length 516.4
  Bottom Layer w6: J12.2@1785.2,1710.94 1799.55,1710.94 1819.24,1691.25 R58.1@1856.12,1691.25 1966.43,1691.25 1986.11,1710.94 2061.68,1710.94 2116.45,1656.17 U4.2@2262.59,1656.17
NetJ13_2: J13.2 R1.1 U20.5 | length 385.9
  Top Layer w6: J13.2@3033.13,388.99 3154.53,510.39 3154.53,598.89 v1(3205.24,649.6) 3239.59,649.6 R1.1@3240.44,648.75
  Bottom Layer w6: v1(3205.24,649.6) 3222.18,649.6 U20.5@3223.28,648.49
NetJ14_1: J14.1 R91.1 U13.5 | length 235
  Bottom Layer w6: R91.1@1346.76,607.44 1346.76,641.71 1369.5,664.46 1382.66,664.46 1463.3,745.09 1463.3,784.94 U13.5@1464.41,786.05
NetJ15_1: J15.1 R2.1 R4.2 R5.2 R63.2 | length 228.1
  Bottom Layer w6: J15.1@1955.98,1308.98 R2.1@1955.98,1364.06 ; R4.2@1955.98,1484.79 R5.2@1955.98,1421.47 R2.1@1955.98,1364.06 ; R63.2@2008.29,1364.06 R2.1@1955.98,1364.06
NetQ3_1: Q3.1 Q3.3 U10.8
NetQ3_2: Q3.2 Q3.4 U10.6 U10.7 | length 188.9
  Bottom Layer w6: U10.7@2830.69,876.71 U10.7@2831.52,875.89
  Bottom Layer w10: Q3.4@2730.69,927.57 2730.69,897.47 2742.27,885.89 U10.6@2811.83,885.89 U10.7@2831.52,885.89 2830.69,886.71 Q3.2@2830.69,937.57
NetQ6_1: Q6.1 U2.20 | length 53.4
  Top Layer w6: v1(1765.17,667.89) 1765.54,667.89 1775.96,657.46 U2.20@1802.8,657.46
  Bottom Layer w6: Q6.1@1765.06,656.48 1765.11,656.53 1765.11,667.83 v1(1765.17,667.89)
NetQ6_3: Q6.3 Q7.1 R34.1 | length 82.5
  Bottom Layer w6: R34.1@1701.35,649.59 Q6.3@1739.47,649.59 1739.47,680.31 1743.31,684.15 1743.31,690.76 Q7.1@1744.47,691.92
NetQ8_4: Q8.4 U12.17 | length 371.7
  Top Layer w6: v1(1637.18,446.59) 1660.81,470.22 1686.61,470.22 U12.17@1686.66,470.17 ; v1(1854.18,348.69) 1854.35,348.86 1854.35,363.69 1858.35,367.68 Q8.4@1872.13,367.68
  Int2 (Sign) w6: v1(1637.18,446.59) 1637.18,411.82 1666.98,382.02 1774.41,382.02 1782.87,373.56 1788.58,373.56 1791.16,370.98 1831.89,370.98 v1(1854.18,348.69)
NetQ15_3: Q15.3 R149.1 | length 50.2
  Top Layer w6: Q15.3@1193.05,1000 R149.1@1243.25,1000
NetQ18_3: Q18.3 R152.1 | length 42.7
  Top Layer w6: Q18.3@1193.05,1294.11 R152.1@1235.75,1294.11
NetQN1_3: QN1.3 R50.1 | length 27.7
  Bottom Layer w6: R50.1@1473.68,440.59 QN1.3@1473.68,468.29
NetQN2_3: QN2.3 R51.1 | length 27.7
  Bottom Layer w6: R51.1@1520.32,440.59 QN2.3@1520.32,468.29
NetQP1_3: QP1.3 R48.2 | length 27.7
  Bottom Layer w6: QP1.3@1473.68,283.74 R48.2@1473.68,311.45
NetQP2_3: QP2.3 R49.2 | length 27.7
  Bottom Layer w6: QP2.3@1520.32,283.74 R49.2@1520.32,311.44
NetR16_2: R16.2 U7.9 | length 213.8
  Bottom Layer w6: U7.9@2823.11,2510.43 2823.11,2489.55 2839.8,2472.86 2934.75,2472.86 ; 2934.87,2472.97 2986.86,2524.97 R16.2@2986.86,2525.75
NetR17_2: R17.2 U7.8 | length 165.7
  Bottom Layer w6: U7.8@2838.86,2510.43 2839.79,2509.49 2839.79,2489.84 2844.77,2484.86 2929.78,2484.86 ; 2929.89,2484.97 2958.1,2513.18 2958.1,2525.32 R17.2@2958.54,2525.75
NetR18_1: R18.1 U9.16 | length 65.4
  Top Layer w6: R18.1@2614.71,2088.33 2616.68,2088.33 2636.07,2068.95 2636.07,2057.17 v1(2637.21,2056.02)
  Bottom Layer w6: U9.16@2614.71,2056.29 2614.84,2056.16 2637.08,2056.16 v1(2637.21,2056.02)
NetR20_1: R20.1 R22.1 U9.18 | length 107.8
  Top Layer w6: R20.1@2659.73,2016.45 R20.1@2660.14,2016.86
  Top Layer w20: v1(2638.05,2016.45) R20.1@2659.73,2016.45 ; R22.1@2660.15,1954.86 R20.1@2660.15,2016.87
  Bottom Layer w6: U9.18@2614.71,2016.92 2614.95,2016.68 2637.82,2016.68 v1(2638.05,2016.45)
NetR21_1: R21.1 R23.2 U9.12 | length 115.1
  Bottom Layer w6: R21.1@2440.64,2108.56 R23.2@2474.55,2108.56 ; R23.2@2474.55,2110.53 R23.2@2474.55,2108.56 ; R23.2@2476.27,2108.56 R23.2@2474.55,2108.56 ; U9.12@2511.41,2080.19 2513.33,2078.27 U9.12@2513.33,2072.04 2486.11,2072.04 2474.55,2083.6 R23.2@2474.55,2108.56
NetR25_2: R25.2 R27.2 R48.1 R50.2 | length 415.2
  Top Layer w6: v1(1591.87,550) 1604.85,562.97 R27.2@1677.7,562.97
  Int2 (Sign) w6: v1(1440.37,417.24) 1440.37,447.38 1542.98,550 v1(1591.87,550)
  Bottom Layer w6: v1(1440.37,417.24) 1440.21,417.08 R25.2@1440.21,401.37 1473.53,401.37 R50.2@1473.68,401.22 R48.1@1473.68,350.82
NetR26_1: R26.1 R28.1 R49.1 R51.2 | length 341.1
  Top Layer w6: v1(1646.21,585.83) 1647.83,585.83 1657.5,595.5 R28.1@1677.7,595.5
  Int2 (Sign) w6: v1(1552.86,415.42) 1552.86,472.65 1620.22,540.01 1620.22,559.85 v1(1646.21,585.83)
  Bottom Layer w6: R49.1@1520.32,350.81 R51.2@1520.32,401.22 1520.48,401.37 R26.1@1551.96,401.37 1551.96,414.52 v1(1552.86,415.42)
NetR31_1: R31.1 U2.5 | length 238.2
  Top Layer w6: U2.5@1954.38,657.46 1991.28,657.46 1995.03,661.21 2040.33,661.21 2133.69,754.57 2133.69,760.73 R31.1@2142.5,769.54
NetR45_1: R45.1 U12.7 | length 84.8
  Top Layer w6: U12.7@1796.9,438.67 1797.03,438.81 1816.54,438.81 v1(1816.67,438.95)
  Bottom Layer w6: v1(1816.67,438.95) 1816.67,395.85 1831.53,380.99 R45.1@1831.53,380.21
NetR46_1: R46.1 U12.6 | length 44.8
  Top Layer w6: U12.6@1796.9,422.92 1797.83,421.99 1801.67,421.99 v1(1801.67,399.43)
  Bottom Layer w6: R46.1@1799.94,383.06 1800.73,383.85 1800.73,398.49 v1(1801.67,399.43)
NetR53_2: R53.2 U14.27 | length 304.1
  Top Layer w6: v1(608.08,2399.68) 608.71,2400.31 608.71,2633.3 v1(609.34,2633.93)
  Bottom Layer w6: R53.2@590.33,2609.52 592.3,2609.52 608.19,2625.42 608.19,2632.79 v1(609.34,2633.93)
  Bottom Layer w10: v1(608.08,2399.68) U14.27@643.96,2399.68
NetR60_1: R60.1 R67.2 Y1.1 | length 160.8
  Bottom Layer w6: R67.2@346.69,2533.93 R60.1@393.81,2533.93 ; R60.1@393.84,2533.96 483.05,2533.96 498.95,2549.86 Y1.1@500.91,2549.86
NetR79_1: R79.1 R80.2 U4.1 | length 111.9
  Bottom Layer w10: R80.2@2202,1578.76 R79.1@2243.81,1578.76 2245.78,1578.76 2268.49,1601.47 U4.1@2268.49,1637.47
NetR81_2: R81.2 U4.9 | length 55.2
  Bottom Layer w10: U4.9@2333.45,1656.17 R81.2@2388.69,1656.17
NetR94_1: R94.1 R95.2 U20.2 | length 113.3
  Bottom Layer w10: R95.2@3274.46,471.34 U20.2@3274.46,538.26
  Bottom Layer w15: R95.2@3274.46,471.34 R94.1@3320.86,471.34
NetU7_15: U7.15 U7.30 U7.40 | length 79.9
  Bottom Layer w6: v3(2716.41,2545.08) 2716.81,2545.08 2728.62,2533.27 U7.15@2728.62,2510.43 ; v3(2716.41,2625.39) 2716.81,2625.39 2728.62,2637.2 U7.30@2728.62,2660.04
  other v3: 2680.98,2545.08 2698.7,2565.16 2680.98,2585.23 2716.41,2585.23 2698.7,2605.31 2680.98,2625.39
NetU14_30: U14.30 Y1.3 | length 75.3
  Bottom Layer w10: Y1.3@568.83,2494.59 569.25,2494.17 U14.30@643.96,2494.17
OSC0: C91.1 U22.40 Y2.3 | length 247.4
  Bottom Layer w6: C91.1@266.27,1730 Y2.3@266.27,1792.69 269.12,1795.54 332.49,1795.54 346.69,1781.34 U22.40@443.94,1781.34
OSC1: C90.1 U22.41 Y2.1 | length 359.9
  Bottom Layer w6: C90.1@179.66,1921.64 Y2.1@179.66,1855.69 216.22,1855.69 225.87,1846.03 225.87,1834.02 235.87,1824.02 335.33,1824.02 358.32,1801.03 U22.41@443.94,1801.03
PD_D_N: J4.A7 J4.B7 R77.2 R89.1 | length 1031.2
  Top Layer w6: R89.1@1153.68,321.51 1153.76,321.59 1153.76,336.29 v1(1153.83,336.36) ; R77.2@1469.1,174.21 v1@1486.91,174.21 ; v1(1491.1,174.58) 1499.96,165.72 1513.87,165.72 1703.81,165.72 1741.34,203.25 v1(1741.34,233.26)
  Bottom Layer w6: v1(1153.83,336.36) 1153.83,334.74 1145.68,326.59 1145.68,125.61 1198.35,72.94 1343.87,72.94 1436.73,165.8 1482.32,165.8 v1(1491.1,174.58) ; v1(1741.34,233.26) 1741.34,267.11 v1(1770.81,296.59)
PD_D_P: J4.A6 J4.B6 R78.2 R90.1 | length 1071.1
  Top Layer w6: R90.1@1125.68,321.51 1125.9,321.73 1125.9,336.09 v1(1126.12,336.3) ; R78.2@1467.76,145.39 1490.1,145.39 v1(1490.65,145.94) ; v1@1489.13,147.45 1490.89,147.45 1497.16,153.72 1508.9,153.72 1708.78,153.72 1760.97,205.91 J4.B6@1760.97,233.59 1758.65,235.91 1758.65,255.23 1751.12,262.76 J4.A6@1751.12,296.59
  Bottom Layer w6: v1(1126.12,336.3) 1126.12,335.85 1133.68,328.29 1133.68,120.64 1193.38,60.94 1348.84,60.94 1441.7,153.8 1482.78,153.8 v1(1490.65,145.94)
PP5V: C43.1 C44.1 J5.A07 J9.1 P1.87 U2.28 U2.29 U4.6 | length 2287.3
  Top Layer w6: v1(2074.52,1736.32) 2074.94,1736.73 P1.87@2074.94,2243.7 ; v1(2590.65,805) 2592,806.35 J5.A07@2592,850
  Top Layer w15: v1(2311.47,1579.35) v1(2311.96,1719.54) ; v1(2312.25,1750.71) 2311.96,1750.42 v1(2311.96,1719.54) ; v1(2497.4,1719.54) v1(2311.96,1719.54)
  Int2 (Sign) w6: v1(2074.52,1736.32) v1(2184,1736.32) ; v1(2379.66,805.63) 2380.29,805 v1(2590.65,805)
  Int2 (Sign) w15: v1(2497.4,1719.54) 2543.83,1673.11 2796.45,1673.11 3097.27,1973.93 3300.31,1973.93 J9.1@3377.95,2051.57
  other v1: 1871.07,537.68 1884.61,537.59 1871.07,551 1884.61,551 2311.62,1594.94 2311.77,1610.52 2312.11,1735.13
PP_EN: J2.15 P1.10 Q7.3 Q18.1@1177.31,1301 R10.2 R35.1 U10.4 | length 5106.1
  Top Layer w6: J2.15@955.88,1350 957.63,1348.25 v1(1127.09,1348.25) 1127.59,1348.25 1174.84,1301 Q18.1@1177.31,1301 ; v1(1153.71,2334.29) P1.10@1153.68,2456.3 ; v1(2692.11,1063.52) 2682.2,1053.62 2682.2,654.42 2740.72,595.9 2892.14,595.9 v1(2892.22,595.98)
  Int2 (Sign) w6: v1(1127.09,1348.25) 1507.77,1348.25 v1(1633.51,1222.52) ; v1(2544.36,1400.39) 2576.57,1400.39 2692.11,1284.86 v1(2692.11,1063.52)
  Bottom Layer w6: v1(1127.09,1348.25) 1127.09,2307.66 v1(1153.71,2334.29) ; v1(1633.51,1222.52) 1633.51,1026.67 1707.19,952.99 1763.72,952.99 1886.95,829.75 1886.95,717.51 ; R35.1@1701.35,717.51 R35.1@1702.11,718.27 ; R35.1@1703.31,717.51 Q7.3@1737.58,717.51 1886.95,717.51 ; v1(2544.36,1400.39) 2366.19,1222.23 2366.19,948.71 2091.3,673.82 1930.64,673.82 1886.95,717.51 ; U10.4@2831.52,710.1 2831.52,676.79 2892.26,616.04 v1@2892.26,595.98 ; R10.2@2892.26,577.44 v1@2892.24,595.96
PPHV: C59.1 D22.1 J7.2 Q3.6 R1.2 R72.2 TP11.1 U20.8 | length 37.2
  Top Layer w6: R1.2@3279.81,648.75 3281.7,646.86 v1(3316.18,646.86)
PPHV1_D10: J5.B09 P1.111 | length 2079.7
  Top Layer w6: v1(2327.25,2086.25) 2358.12,2117.12 2358.12,2243.41 P1.111@2358.41,2243.7 ; v1(2781.66,690.71) 2781.66,672 2803.66,650 J5.B09@2806.96,650
  Int2 (Sign) w6: v1(2327.25,2086.25) 2238.57,1997.57 2238.57,1490.27 2379.72,1349.13 2379.72,975.5 2397.83,957.4 2737.5,957.4 2781.66,913.24 v1(2781.66,690.71)
PPHV_D10: J5.B08 P1.113 R72.1 R74.2 | length 2852.4
  Top Layer w6: P1.113@2382.03,2243.7 2382.34,2243.39 2382.34,2173.18 v1(2382.66,2172.86) ; J5.B08@2806.96,750 2908.82,750 2930.16,771.34 2930.16,1178.93 3060.23,1309 3296.85,1309 3430.51,1442.66 3430.51,1796.46 3238.7,1988.27 3076.96,1988.27 2892.37,2172.86 v1(2892.28,2172.86)
  Int2 (Sign) w6: v1(2382.66,2172.86) v1(2892.28,2172.86)
  Bottom Layer w6: R72.1@3146.67,1309 v1(3181.74,1309) R74.2@3221.15,1309
RP_5V: C58.1 D10.2 L5.2
RP_VBUS: C62.1 C63.1 C64.1 C65.1 C66.1 D4.1 J6.A4 J6.A9 J6.B4 J6.B9 L5.1 U17.4 U17.5 U17.6 | length 513.2
  Top Layer w6: D4.1@442.28,3008.28 504.12,3008.28 557.09,2955.3 C62.1@687.6,2955.3
  Bottom Layer w10.5: J6.B9@752.74,2865.5 v1(752.74,2837.08) 762.58,2827.24 J6.A4@762.3,2802.51 ; J6.B9@752.74,2867.1 v1(752.74,2895.52) ; v1(762.58,2775) J6.A4@762.58,2802.51 ; J6.B4@851.16,2865.5 v1(851.16,2837.08) 861,2827.24 861,2802.51 v1(861,2775) ; J6.B4@851.16,2867.1 v1(851.16,2895.52)
RST: C89.2 D8.2 R98.2 S2.2 U22.38 | length 567.1
  Int2 (Sign) w6: v1(274.15,1656.79) 406.69,1656.79 v1(492.58,1742.68)
  Bottom Layer w6: v1(274.15,1656.79) S2.2@274.15,1603.91 C89.2@274.15,1508.11 R98.2@274.15,1454.56 D8.2@336.04,1454.56 ; U22.38@443.94,1741.97 491.87,1741.97 v1(492.58,1742.68)
SBU1: J5.B03 P1.103 R27.1 U12.15 | length 3041.8
  Top Layer w6: v1@1696.4,541.99 v1(1696.77,541.99) ; R27.1@1699.74,560.97 1699.74,546.58 1696.77,543.61 v1(1696.77,541.99) ; U12.15@1710.28,509.54 1710.28,528.48 v1(1696.77,541.99) ; v1(1779.41,916.08) 2022.41,916.08 2023.98,917.65 2039.36,917.65 2207.98,1086.28 v1(2207.98,1153.2) ; P1.103@2263.92,2243.7 2263.92,2197.83 2268.76,2192.98 v1(2268.76,2176.97) ; v1(2474.18,1188.68) 2475.44,1188.68 2480.7,1183.42 2665.72,1183.42 2732.3,1250 J5.B03@2806.96,1250
  Int2 (Sign) w6: v1(1696.77,541.99) 1716.04,561.25 1716.04,640.84 1744.16,668.97 1744.16,746.82 1800.37,803.02 1800.37,820.28 1758.34,862.31 1758.34,895.01 v1(1779.41,916.08) ; v1(2268.76,2176.97) 2280.76,2188.97 2317.36,2188.97 2354.73,2151.6 v1(2354.73,1455.74) 2354.73,1416.29 2474.18,1296.84 v1(2474.18,1188.68)
  Bottom Layer w6: v1(2207.98,1153.2) 2195.66,1165.52 2195.66,1382.66 2268.74,1455.74 v1(2354.73,1455.74)
SBU2: J5.A03 P1.101 R28.2 U12.14 | length 2747.1
  Top Layer w6: R28.2@1699.74,595.5 v1(1699.74,580.5) 1700.89,579.35 1705.64,579.35 1726.03,558.96 U12.14@1726.03,509.54 ; v1(1713.65,981.84) 2012.01,981.84 2085.43,1055.26 2085.43,1143.91 v1(2106.05,1164.53) ; v1(2228.4,2158.29) 2240.35,2170.24 2240.35,2243.65 P1.101@2240.3,2243.7 ; v1(2337.51,1212.28) 2396.26,1212.28 2434.17,1250.18 2591.82,1250.18 J5.A03@2592,1250
  Int2 (Sign) w6: v1(1699.74,580.5) 1699.74,666.97 1715.02,682.25 1715.02,980.47 v1(1713.65,981.84) ; v1(2106.05,1164.53) 2183.83,1164.53 2252.55,1233.25 2252.55,1353.2 2292.95,1393.6 ; v1(2228.4,2158.29) 2210.25,2140.14 2210.25,1476.29 2292.95,1393.6 ; v1(2337.51,1212.28) 2337.92,1212.68 2337.92,1348.63 2292.95,1393.6
TC_VSYS: C22.1 C23.1 C24.1 C25.1 C26.1 C27.1 C28.1 D1.2 U7.20 U7.21 U7.22 U7.@2645.94,2558.6
VBUS: C8.1 C47.1 D7.2 L4.1 Q3.5 Q8.5 Q8.6 Q8.7 Q8.8 Q8.9 R65.2 TP1.1 U12.20 | length 467
  Top Layer w6: C47.1@1638.17,383.24 1659.01,383.24 v1(1684.65,408.88) 1684.65,421.99 1685.59,422.92 U12.20@1686.66,422.92
  Top Layer w15: TP1.1@2224.88,147.97 D7.2@2224.88,253.66
  Int2 (Sign) w6: v1(1684.65,408.88) 1749.52,408.88 1755.07,414.43 1831.13,414.43 1867.91,377.65 1879.25,377.65 1889.33,367.58 v4@1951.64,367.58
  other v2: 2005.08,404.94
  other v4: 1951.64,366.55 1987.27,366.55 1933.82,404.94 1969.45,404.94 1951.64,443.32 1987.27,443.32
VBUS_C: C37.2 C38.1 C39.1 C40.1 C41.1 J4.A4 J4.A9 J4.B4 J4.B9 L4.2 | length 233.4
  Top Layer w6: v1(1701.76,212.45) v1@1701.84,212.52 ; J4.B9@1701.84,233.52 J4.B9@1701.91,233.59 J4.B9@1701.91,233.59
  Top Layer w10: v1@1701.84,212.52 J4.B9@1701.84,233.52 ; J4.B9@1701.91,233.59 v1(1701.84,256.78) 1702.22,257.16 1702.22,264.38 1706.34,268.51 v1(1706.34,269.05) 1706.34,269.59 1711.44,274.68 1711.44,296.27 J4.A4@1711.75,296.59 1711.44,296.9 1711.44,317.11 1705.26,323.29 v1(1705.26,323.83) ; v1(1800.34,212.6) J4.B4@1800.34,233.59 ; J4.B4@1800.34,233.59 v1(1800.38,258.65) 1800.38,259.1 1809.88,268.6 v1(1809.88,269.05) J4.A9@1809.88,296.29 ; J4.A9@1810.03,296.44 J4.A9@1810.18,296.59 v1(1810.18,323.83)
VBUS_D10: J5.A08 P1.117 R65.1 R69.2 | length 1873.3
  Top Layer w6: v1(2337.51,750) J5.A08@2592,750 ; P1.117@2429.27,2243.7 2429.55,2243.42 2429.55,2146.08 v1(2429.83,2145.8) v1@2429.55,2145.52 ; 2509.4,751.5 v1(2509.4,992.02)
  Int2 (Sign) w6: v1(2429.83,2145.8) 2429.83,2119.29 2457.3,2091.82 2457.3,1549.22 2473.94,1532.58 2473.94,1400.03 2549.03,1324.94 2549.03,1031.65 v1(2509.4,992.02)
  Bottom Layer w6: R69.2@2305.97,750 R65.1@2366.19,750
VBUS_LV: C3.1 C48.1 Q8.1 Q8.2 Q8.3 R71.2 TP2.1 U2.26 U2.27 U12.19 | length 1243.1
  Top Layer w6: C48.1@1638.17,422.69 1640.14,422.69 1656.26,438.81 1686.52,438.81 U12.19@1686.66,438.67 ; TP2.1@2565.47,162 TP2.1@2574.04,162
  Top Layer w15: v1(1862.15,475.09) 1866.93,479.87 2247.6,479.87 TP2.1@2565.47,162 ; TP2.1@2574.04,162 2620.5,208.47 R71.2@2669.2,208.47
  Int2 (Sign) w6: v1(1668.01,438.95) 1714.62,485.56 1722.65,485.56 1733.97,496.88 1763.23,496.88 1778.11,482.01 1807.37,482.01 1808.31,482.95 1825.57,482.95 1828.1,482.95 1828.17,482.87 1852.76,482.87 1860.53,475.09 v1(1862.15,475.09)
  other v1: 1848.64,525.79 1848.64,539.1 1848.64,552.42
VBUS_LV_D10: J5.A09 P1.115 R71.1 R73.2 | length 2403.5
  Top Layer w6: v1(2405.47,2060.71) 2405.56,2060.8 2405.56,2243.61 P1.115@2405.65,2243.7 ; v1(2430.49,776.65) 2430.49,994.74 v1(2450.48,1014.73) ; v1(2502.75,648.75) 2503.99,650 J5.A09@2592,650
  Top Layer w15: J5.A09@2592,650 2609.5,632.5 2649.32,632.5 2708.57,573.25 R71.1@2708.57,208.47 R73.2@2708.57,162
  Int2 (Sign) w6: v1(2405.47,2060.71) 2405.47,2027 2406.69,2025.77 2406.69,2013.34 2405.47,2012.12 2405.47,1559.05 2447.17,1517.34 2447.17,1381.61 2512.92,1315.87 2512.92,1042.99 2484.65,1014.72 v1(2450.48,1014.73) ; v1(2430.49,776.65) 2430.49,670.69 2452.43,648.75 v1(2502.75,648.75)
